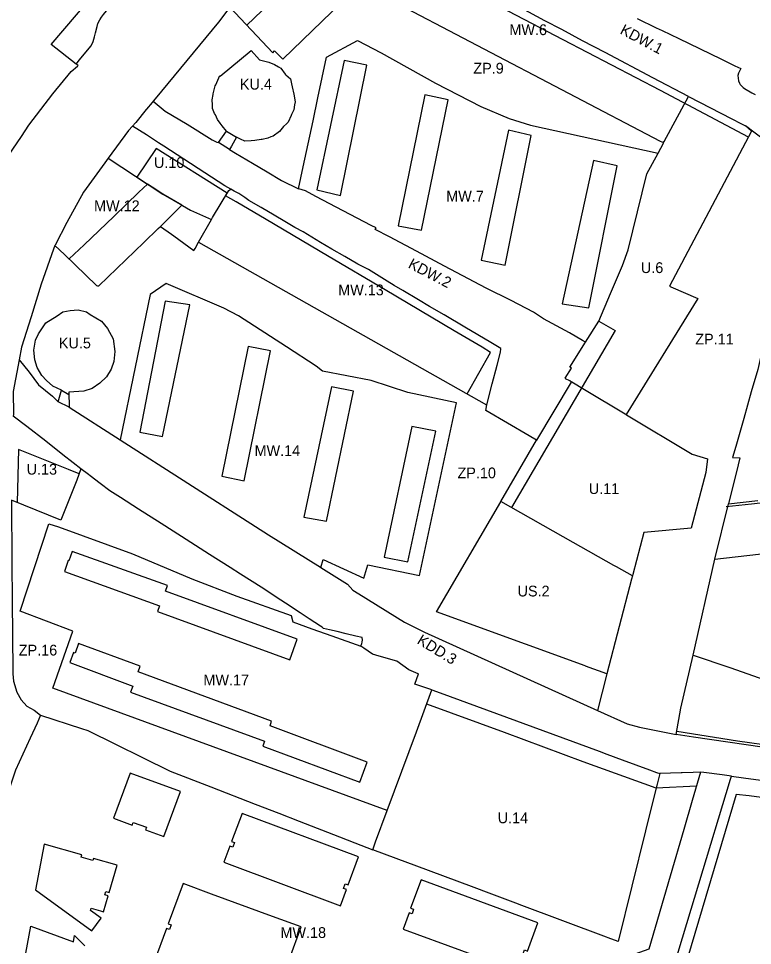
# Model space of a CAD drawing. Extents: x 7428689 to 7430424, y 5549101 to 5550539.
# Drawn here: x 7429558.3 to 7429899, y 5549654.2 to 5550084.5 of the extents above; entities that cross this region are included whole.
import ezdxf

# ---------------------------------------------------------------- set-up
doc = ezdxf.new("R2010")
doc.units = 0
for name, color, linetype in [('linie rozgraniczające', 7, 'Continuous'), ('nieprzekraczalne linie zabudowy', 7, 'Continuous'), ('obowiazujace linie zabudowy', 7, 'Continuous'), ('przeznaczenia terenów', 7, 'Continuous')]:
    doc.layers.add(name, color=color, linetype=linetype)

msp = doc.modelspace()

# ---------------------------------------------------------------- linework, layer by layer
at = {"layer": 'linie rozgraniczające'}
for points in [[(7429585.15, 5550063.36), (7429573.41, 5550072.44), (7429615.16, 5550121.37), (7429623.18, 5550131.69), (7429628.73, 5550142.8), (7429633.73, 5550156.94), (7429637.36, 5550170.6), (7429637.27, 5550178.76), (7429635.82, 5550186.66), (7429632.23, 5550195.98), (7429627.06, 5550204.65), (7429621.44, 5550211.32), (7429578.76, 5550241.61), (7429461.51, 5550318.42), (7429387.53, 5550346.57)], [(7429869.25, 5550048.21), (7429852.78, 5550056.98), (7429830.56, 5550068.73), (7429820.17, 5550074.14), (7429810.58, 5550079.43), (7429802.65, 5550083.47), (7429791.4, 5550089.42), (7429780.49, 5550095.18), (7429764.74, 5550103.58), (7429759.94, 5550106.04), (7429756.81, 5550108.06), (7429752.32, 5550110.84), (7429748.27, 5550113.3), (7429743.03, 5550117.31), (7429741.17, 5550118.66)], [(7429585.15, 5550063.36), (7429586.69, 5550065.24), (7429591.91, 5550071.67), (7429592.5, 5550072.73), (7429592.96, 5550073.85), (7429593.59, 5550076), (7429593.98, 5550077.82), (7429594.75, 5550080.83), (7429595.18, 5550082.22), (7429596.04, 5550083.81), (7429596.76, 5550085.13), (7429597.72, 5550086.32), (7429603.54, 5550093.53), (7429609.86, 5550101.47), (7429615.12, 5550107.92), (7429618.82, 5550112.61), (7429620.13, 5550114.03)], [(7429656.47, 5550089.67), (7429676.37, 5550068.6), (7429677.06, 5550069.42), (7429681.08, 5550065.54), (7429712.8, 5550096.5), (7429725.68, 5550089.53), (7429728.53, 5550094.56)], [(7429728.53, 5550094.56), (7429856.2, 5550027.54), (7429857.77, 5550026.87)], [(7429656.47, 5550089.67), (7429651.14, 5550082.75), (7429621.81, 5550047.22), (7429620.82, 5550046.08)], [(7429845.5, 5550084.48), (7429854.32, 5550080.21), (7429857.1, 5550078.87), (7429864.74, 5550075.17), (7429884.25, 5550065.73), (7429890.82, 5550062.56), (7429893.52, 5550061.26), (7429892.52, 5550059.16), (7429892.26, 5550058.1), (7429892.29, 5550056.74), (7429892.49, 5550055.49), (7429892.92, 5550054.49), (7429893.29, 5550053.87), (7429894.37, 5550052.7), (7429894.69, 5550052.4), (7429895.26, 5550051.95), (7429898.75, 5550050.01), (7429900.22, 5550049.26)], [(7429688.27, 5550005.48), (7429690.46, 5550015.68), (7429695.11, 5550037.01), (7429697.29, 5550047.68), (7429701.34, 5550066.55), (7429715.73, 5550074.25), (7429726.71, 5550068.51), (7429751.94, 5550054.46), (7429772.96, 5550043.69), (7429786.09, 5550038.05), (7429795.94, 5550034.97), (7429855.15, 5550022.01)], [(7429651.13, 5550026.86), (7429654.92, 5550032.22), (7429652.8, 5550034.62), (7429651.9, 5550035.89), (7429650.66, 5550037.64), (7429649.69, 5550039.72), (7429649.35, 5550040.46), (7429648.32, 5550042.77), (7429648.28, 5550044.39), (7429648.21, 5550046.78), (7429648.66, 5550049.14), (7429648.72, 5550049.48), (7429649.67, 5550053.25), (7429649.93, 5550053.77), (7429651.72, 5550057.99), (7429651.92, 5550057.78), (7429666.37, 5550069.7), (7429670.18, 5550065.35), (7429674.49, 5550064.22), (7429677.11, 5550063.11), (7429679, 5550062.04), (7429680.08, 5550061.42), (7429682.04, 5550058.67), (7429682.44, 5550058.31), (7429684.56, 5550056.41), (7429685.07, 5550054.13), (7429685.37, 5550052.78), (7429686.14, 5550049.3), (7429686.73, 5550045.82), (7429686.47, 5550044.37), (7429686.07, 5550042.16), (7429685.08, 5550039.91), (7429684.87, 5550039.44), (7429683.41, 5550036.39), (7429682.66, 5550035.54), (7429681.28, 5550034.29), (7429679.5, 5550032.04), (7429676.45, 5550029.92), (7429675.42, 5550029.52), (7429674, 5550028.95), (7429671.4, 5550028.34), (7429670.93, 5550028.27), (7429668.07, 5550027.81), (7429666.23, 5550027.68), (7429663.32, 5550027.47), (7429661.32, 5550028.49), (7429659.54, 5550029.4), (7429657.11, 5550025.19), (7429656.27, 5550023.71)], [(7429553.73, 5550020.94), (7429559.75, 5550029.69), (7429563.14, 5550035.03), (7429574.24, 5550049.55), (7429582.68, 5550059.88), (7429585.76, 5550062.39), (7429586.07, 5550062.64), (7429585.15, 5550063.36)], [(7429620.82, 5550046.08), (7429620.29, 5550045.47), (7429617.65, 5550042.43), (7429617.5, 5550042.26), (7429612.74, 5550036.22), (7429612.59, 5550036.02), (7429611.21, 5550034.49)], [(7429620.82, 5550046.08), (7429626.45, 5550041.42), (7429636.61, 5550035.39), (7429648.2, 5550028.09), (7429650.34, 5550027.09), (7429651.13, 5550026.86)], [(7429857.77, 5550026.87), (7429858.08, 5550027.46), (7429869.25, 5550048.21)], [(7429869.25, 5550048.21), (7429889.41, 5550037.88), (7429893.56, 5550035.76), (7429895.81, 5550034.62)], [(7429611.21, 5550034.49), (7429609.44, 5550032.52), (7429599.97, 5550019.58)], [(7429656.81, 5550005.3), (7429654.12, 5550006.82), (7429625.7, 5550025.24), (7429623.31, 5550026.82), (7429620.09, 5550028.95), (7429617.74, 5550030.44), (7429611.21, 5550034.49)], [(7429895.81, 5550034.62), (7429898.57, 5550032.25), (7429860.52, 5549960.24), (7429861.09, 5549960), (7429873.67, 5549954.52), (7429840.39, 5549900.6)], [(7429916.81, 5549969.68), (7429907.37, 5549981.28), (7429907.97, 5549984.97), (7429910.62, 5549999.1), (7429912.84, 5550010.27), (7429915.01, 5550020.22), (7429913.54, 5550021.3), (7429904.69, 5550027.9), (7429895.81, 5550034.62)], [(7429656.27, 5550023.71), (7429651.13, 5550026.86)], [(7429855.15, 5550022.01), (7429857.65, 5550026.66), (7429857.7, 5550026.75), (7429857.77, 5550026.87)], [(7429599.97, 5550019.58), (7429598.41, 5550017.45), (7429588.53, 5550003.91), (7429580.8, 5549989.73), (7429575.28, 5549979.34), (7429575.19, 5549979.09)], [(7429599.97, 5550019.58), (7429625.37, 5550002.89), (7429634.45, 5549997.69), (7429638.12, 5549995.59), (7429647.87, 5549991.13)], [(7429656.27, 5550023.71), (7429659.03, 5550022.01), (7429666.97, 5550017.37), (7429673.68, 5550013.28), (7429680.38, 5550009.23), (7429688.27, 5550005.48)], [(7429821.51, 5549934.28), (7429827.64, 5549943.96), (7429833.14, 5549956.88), (7429838.63, 5549969.77), (7429841.32, 5549977.09), (7429849.95, 5550012.35), (7429855.15, 5550022.01)], [(7429647.87, 5549991.13), (7429648.39, 5549992.05), (7429655.88, 5550004.65), (7429656.81, 5550005.3)], [(7429775.71, 5549905.16), (7429778.18, 5549914.86), (7429780.43, 5549923.59), (7429782.03, 5549929.66), (7429782.15, 5549931.13), (7429782.12, 5549931.33), (7429777.49, 5549934.06), (7429765.48, 5549941.2), (7429755.86, 5549946.89), (7429749.11, 5549950.82), (7429744.02, 5549953.83), (7429736.71, 5549958.17), (7429732.74, 5549960.55), (7429729.37, 5549962.63), (7429720.7, 5549967.99), (7429715.87, 5549970.5), (7429709.82, 5549973.94), (7429703.74, 5549977.38), (7429698.51, 5549980.56), (7429690.37, 5549985.39), (7429686.54, 5549987.54), (7429681.97, 5549990.21), (7429676.95, 5549993.16), (7429670.93, 5549996.73), (7429665.27, 5550000.04), (7429663.42, 5550001.36), (7429660.54, 5550003.25), (7429658.48, 5550004.36), (7429656.81, 5550005.3)], [(7429821.51, 5549934.28), (7429820.08, 5549935.1), (7429814.09, 5549938.6), (7429802.03, 5549945.01), (7429797.37, 5549948.18), (7429786.94, 5549953.53), (7429775.41, 5549959.29), (7429761.62, 5549966.57), (7429756.07, 5549969.55), (7429743.09, 5549976.49), (7429730.55, 5549983.08), (7429723.92, 5549986.61), (7429724.28, 5549987.29), (7429722.06, 5549988.44), (7429709.08, 5549995.18), (7429696.34, 5550001.93), (7429691.54, 5550004.51), (7429688.48, 5550005.38), (7429688.27, 5550005.48)], [(7429641.91, 5549980.59), (7429647.87, 5549991.13)], [(7429575.19, 5549979.09), (7429579.7, 5549974.98), (7429594.49, 5549960.54), (7429594.96, 5549960.46), (7429595.63, 5549960.35), (7429616.41, 5549980.48), (7429623.1, 5549986.97), (7429624.28, 5549987.95), (7429629.33, 5549984.32), (7429630.37, 5549983.57), (7429639.77, 5549976.81), (7429640.31, 5549977.78), (7429641.91, 5549980.59)], [(7429575.19, 5549979.09), (7429574.6, 5549977.43), (7429568.87, 5549961.23), (7429564.13, 5549945.96), (7429559.75, 5549931.92), (7429558.64, 5549926.07)], [(7429641.91, 5549980.59), (7429775.53, 5549905.21), (7429775.71, 5549905.16)], [(7429698.6, 5549829.7), (7429699.7, 5549833.33), (7429718.56, 5549824.72), (7429720.51, 5549830.92), (7429744.47, 5549825.99), (7429761.67, 5549906.09), (7429739.1, 5549910.82), (7429722.02, 5549916.42), (7429699.4, 5549920.83), (7429696.47, 5549923.12), (7429682.75, 5549932.04), (7429660.38, 5549946.53), (7429653.56, 5549949.96), (7429626.86, 5549961.43), (7429619.36, 5549956.45), (7429605.47, 5549888.95)], [(7429576.65, 5549906.55), (7429578.22, 5549912.02), (7429574.18, 5549913.77), (7429571.3, 5549916.43), (7429569.09, 5549918.74), (7429567.04, 5549922.44), (7429565.88, 5549926.02), (7429565.47, 5549930.46), (7429566.26, 5549935.15), (7429567.62, 5549938.12), (7429571, 5549943.26), (7429576.28, 5549946.46), (7429578.81, 5549948.33), (7429582.28, 5549949.01), (7429586.07, 5549949.23), (7429589.8, 5549948.28), (7429591.51, 5549947.07), (7429596.84, 5549943.94), (7429599.62, 5549940.56), (7429602.28, 5549935.82), (7429603.01, 5549929.94), (7429602.61, 5549925.21), (7429601.34, 5549921.75), (7429599.11, 5549918.1), (7429595.99, 5549915.26), (7429592.43, 5549912.76), (7429588.61, 5549911.44), (7429581.71, 5549911.07), (7429581.84, 5549904.08)], [(7429908.04, 5549945.59), (7429906.58, 5549941.5), (7429906.31, 5549940.37), (7429905.33, 5549936.24), (7429903.54, 5549929.81), (7429902.43, 5549925.68), (7429901.44, 5549921.63), (7429898.46, 5549911.23), (7429894.97, 5549898.89), (7429891.24, 5549885.87), (7429889.75, 5549880.65), (7429893.15, 5549880.55), (7429892.34, 5549877.29), (7429887.85, 5549859.16)], [(7429815.02, 5549915.74), (7429814.2, 5549916.27), (7429812.23, 5549917.24), (7429812.36, 5549917.46), (7429812.12, 5549917.61), (7429815, 5549922.15), (7429814.16, 5549922.6), (7429821.51, 5549934.28)], [(7429558.64, 5549926.07), (7429555.84, 5549911.31), (7429555.96, 5549900.64), (7429555.91, 5549899.93)], [(7429558.64, 5549926.07), (7429563.23, 5549920.28), (7429565.38, 5549917.32), (7429567.66, 5549914.4), (7429570.78, 5549911.81), (7429574.07, 5549909.18), (7429576.65, 5549906.55)], [(7429798.74, 5549888.73), (7429798.86, 5549888.8), (7429815.02, 5549915.74)], [(7429815.02, 5549915.74), (7429815.08, 5549915.84), (7429820.95, 5549912.3), (7429839.86, 5549900.92), (7429840.29, 5549900.67), (7429840.33, 5549900.64), (7429840.37, 5549900.62), (7429840.39, 5549900.6)], [(7429581.84, 5549904.08), (7429576.65, 5549906.55)], [(7429581.84, 5549904.08), (7429605.47, 5549888.95)], [(7429798.74, 5549888.73), (7429795.33, 5549890.77), (7429795.33, 5549890.77), (7429775.26, 5549902.48), (7429775.7, 5549905.11), (7429775.71, 5549905.16)], [(7429587.28, 5549875.53), (7429583.64, 5549878.26), (7429578.91, 5549881.96), (7429571.02, 5549888.23), (7429562.2, 5549895.06), (7429555.91, 5549899.93)], [(7429840.39, 5549900.6), (7429840.53, 5549900.52), (7429871, 5549882.19), (7429878.11, 5549880.16), (7429877.35, 5549873.76), (7429870.51, 5549847.99), (7429848.5, 5549845.97), (7429843.41, 5549826.45), (7429843.25, 5549825.85)], [(7429605.47, 5549888.95), (7429668.39, 5549848.65), (7429674.4, 5549844.88), (7429698.48, 5549829.77), (7429698.6, 5549829.7)], [(7429782.23, 5549860.32), (7429798.8, 5549888.7), (7429798.74, 5549888.73)], [(7429587.28, 5549875.53), (7429585.37, 5549870.27), (7429577.93, 5549851.65), (7429555.12, 5549860.89)], [(7429717.15, 5549793.18), (7429717.65, 5549794.33), (7429717.83, 5549794.94), (7429717.92, 5549796.1), (7429717.86, 5549797.16), (7429714.91, 5549797.81), (7429710.35, 5549798.91), (7429706.16, 5549799.92), (7429702.65, 5549800.75), (7429699.87, 5549801.38), (7429699.27, 5549801.89), (7429698.41, 5549802.45), (7429693.3, 5549805.81), (7429689.08, 5549808.56), (7429682.25, 5549813.05), (7429680.05, 5549814.49), (7429670.87, 5549820.47), (7429661.35, 5549826.55), (7429656.53, 5549829.67), (7429646.99, 5549835.76), (7429644.78, 5549837.16), (7429634.01, 5549844.04), (7429624.57, 5549850.1), (7429614.01, 5549856.79), (7429605.65, 5549862.11), (7429600.76, 5549865.23), (7429596.23, 5549868.65), (7429591.52, 5549872.22), (7429590.83, 5549872.76), (7429587.28, 5549875.53)], [(7429555.12, 5549860.89), (7429555.15, 5549831.51), (7429555.33, 5549814.51), (7429555.69, 5549781.51), (7429555.75, 5549780.34), (7429555.92, 5549776.94), (7429557.49, 5549771.72), (7429559.59, 5549768.26), (7429562.25, 5549765.37), (7429565.54, 5549763.41), (7429568.57, 5549761.09)], [(7429831.36, 5549780.26), (7429821.48, 5549783.89), (7429821.47, 5549783.87), (7429821.27, 5549783.97), (7429793.68, 5549794.12), (7429752.32, 5549809.11), (7429782.14, 5549860.17), (7429782.23, 5549860.32)], [(7429843.25, 5549825.85), (7429835.93, 5549829.96), (7429834.7, 5549830.53), (7429815.76, 5549841.29), (7429782.23, 5549860.32)], [(7429887.85, 5549859.16), (7429901.45, 5549860.72)], [(7429881.49, 5549833.5), (7429887.85, 5549859.16)], [(7429729.46, 5549716.86), (7429574.24, 5549773.58), (7429583.5, 5549800.05), (7429559.02, 5549809.34), (7429572.42, 5549849.96), (7429576.87, 5549848.51), (7429611.2, 5549835.98), (7429638.72, 5549824.44), (7429659.6, 5549816.36), (7429684.83, 5549807.41), (7429685.69, 5549804.41), (7429694.53, 5549801.26), (7429703.68, 5549797.99), (7429717.15, 5549793.18)], [(7429881.49, 5549833.5), (7429958.54, 5549842.32), (7429958.76, 5549842.35), (7429962.6, 5549842.78), (7429964.4, 5549841.52)], [(7429871.39, 5549789.01), (7429881.49, 5549833.5)], [(7429698.6, 5549829.7), (7429711.07, 5549821.88), (7429713.45, 5549819.07), (7429716.22, 5549817.37), (7429737.5, 5549804.29), (7429739.28, 5549803.41), (7429746.82, 5549799.7), (7429826.99, 5549763.34)], [(7429843.25, 5549825.85), (7429842.81, 5549824.17), (7429831.36, 5549780.26)], [(7429871.39, 5549789.01), (7429888.46, 5549783.29), (7429915.65, 5549773.69), (7429915.92, 5549774.62), (7429916.18, 5549775.67), (7429916.58, 5549776.86), (7429927.23, 5549807.18), (7429960.39, 5549810.65), (7429966.5, 5549811.25)], [(7429750.24, 5549772.92), (7429742.27, 5549775.43), (7429744.01, 5549780.24), (7429743.82, 5549780.31), (7429739.45, 5549782.12), (7429733.95, 5549786.18), (7429730.03, 5549787.31), (7429724.14, 5549789.01), (7429722.65, 5549789.44), (7429718.56, 5549792.22), (7429717.2, 5549793.15), (7429717.18, 5549793.16), (7429717.15, 5549793.18)], [(7429863.62, 5549752.17), (7429865.79, 5549764.38), (7429871.39, 5549789.01)], [(7429831.36, 5549780.26), (7429826.99, 5549763.34)], [(7429729.46, 5549716.86), (7429743.02, 5549753.43), (7429750.24, 5549772.92)], [(7429750.24, 5549772.92), (7429754.07, 5549771.51), (7429827.76, 5549744.4), (7429831.38, 5549743.07), (7429838.58, 5549740.42), (7429851.16, 5549735.8), (7429854.51, 5549734.56), (7429855.96, 5549734.03)], [(7429826.99, 5549763.34), (7429840.89, 5549757.04), (7429846.58, 5549755.58), (7429863.62, 5549752.17)], [(7429568.57, 5549761.09), (7429566.9, 5549757.41), (7429563.77, 5549750.49), (7429556.99, 5549735.53), (7429550.49, 5549716.1), (7429548.76, 5549710.94), (7429543.38, 5549697.43), (7429542.37, 5549694.89), (7429541.35, 5549692.35), (7429533.82, 5549674.3), (7429517.9, 5549636.16)], [(7429568.57, 5549761.09), (7429587.61, 5549754.98), (7429590.55, 5549754.04), (7429628.68, 5549735.16), (7429647.54, 5549727.85), (7429668.13, 5549719.86), (7429679.17, 5549715.57), (7429688.64, 5549711.89), (7429707.29, 5549704.67), (7429714.46, 5549701.87), (7429722.71, 5549698.67)], [(7429974.57, 5549743.68), (7429969.96, 5549745.05), (7429968.9, 5549744.66), (7429967.51, 5549744.92), (7429963.01, 5549746.11), (7429960.03, 5549747.24), (7429956.2, 5549748.63), (7429951.17, 5549747.9), (7429935.89, 5549745.52), (7429925.52, 5549743.92), (7429912.08, 5549744.96), (7429871.59, 5549750.98), (7429863.62, 5549752.17)], [(7429855.96, 5549734.03), (7429854.72, 5549729.03), (7429851.54, 5549716.18), (7429849.36, 5549707.35), (7429836.65, 5549656.01), (7429831.95, 5549657.76), (7429831.26, 5549658.03), (7429811, 5549665.61), (7429790.7, 5549673.21), (7429790.34, 5549673.35), (7429776.79, 5549678.42), (7429769.74, 5549681.06), (7429748.67, 5549688.95), (7429728.18, 5549696.62), (7429722.71, 5549698.67)], [(7429874.89, 5549734.7), (7429871.05, 5549721.57), (7429867.1, 5549708.07), (7429860.77, 5549686.41), (7429850.86, 5549652.48), (7429833.04, 5549646.21), (7429826.11, 5549643.78), (7429821.7, 5549626.48), (7429820.08, 5549620.15), (7429815.04, 5549600.39), (7429808.19, 5549573.55), (7429806.7, 5549567.69), (7429794.73, 5549521.42)], [(7429794.73, 5549521.42), (7429797.12, 5549519.53), (7429807.08, 5549514.9), (7429812.41, 5549529.87), (7429821.23, 5549563.96), (7429822.73, 5549569.85), (7429829.57, 5549596.68), (7429834.43, 5549615.7), (7429834.96, 5549617.8), (7429837.91, 5549624.28), (7429839.87, 5549627.8), (7429842.86, 5549631.59), (7429845.37, 5549632.76), (7429847.45, 5549633.73), (7429851.99, 5549635.55), (7429857.84, 5549637.43), (7429859.86, 5549638.13), (7429860.9, 5549639.29), (7429874.12, 5549682.86), (7429888.83, 5549731.35), (7429889.26, 5549732.78)], [(7429874.89, 5549734.7), (7429871.5, 5549734.58), (7429866.36, 5549734.4), (7429865.82, 5549734.38), (7429855.96, 5549734.03)], [(7429889.26, 5549732.78), (7429885, 5549733.35), (7429876.36, 5549734.5), (7429874.89, 5549734.7)], [(7429889.26, 5549732.78), (7429894.89, 5549732.03), (7429902.84, 5549730.96)], [(7429722.71, 5549698.67), (7429724.04, 5549702.26), (7429729.46, 5549716.86)], [(7429560.16, 5549642.3), (7429563.96, 5549663.23), (7429583.8, 5549655.95), (7429584.34, 5549658.87), (7429589.13, 5549654)]]:
    msp.add_lwpolyline(points, dxfattribs=at)
at = {"layer": 'nieprzekraczalne linie zabudowy'}
for points in [[(7429897.08, 5550029.43), (7429856.35, 5550050.99), (7429811.15, 5550074.65), (7429774.92, 5550093.62), (7429753.78, 5550104.68), (7429737.98, 5550113.04), (7429740.7, 5550118.36), (7429741.17, 5550118.66), (7429714.95, 5550142.63), (7429697.59, 5550122.98), (7429702.3, 5550117.95), (7429664.22, 5550081.46)], [(7429654.92, 5550032.22), (7429659.54, 5550029.4)], [(7429766.58, 5549910.25), (7429777.46, 5549929.53), (7429773.46, 5549931.93), (7429760.54, 5549939.57), (7429728.5, 5549958.49), (7429701.68, 5549974.34), (7429673.24, 5549991.14), (7429659.28, 5549999.39), (7429654.44, 5550002.22), (7429655.19, 5550003.48), (7429622.2, 5550024.07), (7429613.31, 5550010.81), (7429618.12, 5550007.66), (7429614.21, 5550003.83), (7429602.56, 5549992.65), (7429588.78, 5549979.49), (7429581.87, 5549972.98)], [(7429624.28, 5549987.95), (7429634.1, 5549997.89), (7429625.37, 5550002.89), (7429622.05, 5550005.07), (7429618.12, 5550007.66)], [(7429827.64, 5549943.96), (7429835.28, 5549939.73), (7429787.2, 5549857.5)], [(7429578.22, 5549912.02), (7429581.73, 5549909.89)], [(7429586.41, 5549873.13), (7429581.57, 5549875.09), (7429558.37, 5549884.38), (7429557.75, 5549859.82)], [(7430111.57, 5549802.73), (7430095, 5549809.98), (7430066.31, 5549822.5), (7430009.14, 5549847.36), (7429973.71, 5549862.79), (7429955.71, 5549865.8), (7429945.64, 5549864.49), (7429898.6, 5549859.06), (7429886.83, 5549857.85)], [(7429872.96, 5549728.09), (7429872.96, 5549728.09), (7429854.28, 5549727.25), (7429820.43, 5549739.5), (7429783.92, 5549753.02), (7429747.78, 5549766.28)], [(7429863.89, 5549753.68), (7429892, 5549749.19), (7429909.82, 5549746.79), (7429925.29, 5549745.77), (7429964.11, 5549750.56), (7429974.36, 5549747.45)], [(7430250.82, 5549741.6), (7430250.19, 5549740.76), (7430211.41, 5549693.45), (7430176.25, 5549664.73), (7430150.63, 5549651.76), (7430140.11, 5549645.96), (7430038.01, 5549679.61), (7430014.8, 5549687.97), (7429975.18, 5549702.22), (7429941.88, 5549714.17), (7429926.22, 5549719.76), (7429897.47, 5549723.61), (7429891.43, 5549724.32), (7429865.45, 5549636.95), (7429840.64, 5549623.35), (7429816.77, 5549526.64), (7429810.79, 5549500.32)]]:
    msp.add_lwpolyline(points, dxfattribs=at)
at = {"layer": 'obowiazujace linie zabudowy'}
for points in [[(7429709.41, 5550064.98), (7429696.73, 5550004.93), (7429707.76, 5550002.35), (7429719.97, 5550062.77), (7429709.41, 5550064.98)], [(7429745.34, 5549986.28), (7429757.72, 5550046.7), (7429746.85, 5550048.99), (7429734.47, 5549988.24), (7429745.34, 5549986.28)], [(7429784.17, 5549970), (7429796.34, 5550030.18), (7429785.68, 5550032.72), (7429773.05, 5549972.32), (7429784.17, 5549970)], [(7429825.2, 5550018.62), (7429810.71, 5549952.08), (7429823.05, 5549950.16), (7429836.14, 5550016.17), (7429825.2, 5550018.62)], [(7429626.44, 5549953.33), (7429614.62, 5549892.51), (7429625.09, 5549890.49), (7429637.79, 5549951.56), (7429626.44, 5549953.33)], [(7429663.04, 5549869.88), (7429675.21, 5549930.18), (7429664.95, 5549932.28), (7429652.63, 5549872.02), (7429663.04, 5549869.88)], [(7429701.21, 5549851.18), (7429713.86, 5549911.56), (7429703.53, 5549913.58), (7429690.68, 5549853.08), (7429701.21, 5549851.18)], [(7429739.05, 5549832.28), (7429751.97, 5549892.89), (7429740.89, 5549895.13), (7429728.05, 5549834.49), (7429739.05, 5549832.28)], [(7429687.72, 5549796.38), (7429626.49, 5549818.71), (7429627.4, 5549821.33), (7429583.27, 5549837.02), (7429581.62, 5549832.82), (7429581.41, 5549832.89), (7429579.67, 5549827.74), (7429623.77, 5549811.83), (7429622.84, 5549809.3), (7429684.23, 5549786.75), (7429687.72, 5549796.38)], [(7429582.11, 5549785.49), (7429611.4, 5549774.65), (7429610.35, 5549771.72), (7429672.51, 5549749.06), (7429671.77, 5549746.73), (7429716.77, 5549729.98), (7429720.15, 5549739.37), (7429675.07, 5549756.21), (7429675.72, 5549758.34), (7429613.82, 5549781.21), (7429614.75, 5549783.9), (7429586.21, 5549794.43), (7429584.54, 5549789.94), (7429583.82, 5549790.14), (7429582.11, 5549785.49)], [(7429570.28, 5549701.28), (7429566.17, 5549680.01), (7429592.32, 5549660.99), (7429596.66, 5549666.91), (7429591.78, 5549670.49), (7429592.09, 5549671.54), (7429596.41, 5549670.29), (7429597.72, 5549669.9), (7429599.88, 5549677.26), (7429598.44, 5549677.68), (7429598.9, 5549679.3), (7429600.34, 5549678.88), (7429604.03, 5549691.51), (7429593.13, 5549694.65), (7429592.84, 5549693.64), (7429587.44, 5549695.2), (7429587.71, 5549696.24), (7429570.28, 5549701.28)], [(7429634.67, 5549682.96), (7429627.78, 5549664.27), (7429629.19, 5549663.76), (7429628.39, 5549661.59), (7429626.99, 5549662.11), (7429621.26, 5549646.57), (7429634.54, 5549641.72), (7429662.96, 5549631.28), (7429676.17, 5549626.4), (7429683.3, 5549645.83), (7429681.89, 5549646.35), (7429682.69, 5549648.53), (7429684.1, 5549648.02), (7429689.53, 5549662.81), (7429676.28, 5549667.64), (7429647.95, 5549678.07), (7429634.67, 5549682.96)]]:
    msp.add_lwpolyline(points, dxfattribs=at)
for points in [[(7429602.44, 5549713.26), (7429611.06, 5549710.1), (7429611.51, 5549711.32), (7429617.65, 5549709.06), (7429617.22, 5549707.89), (7429625.76, 5549704.72), (7429633.45, 5549725.66), (7429610.11, 5549734.23)], [(7429662.07, 5549715.54), (7429657.15, 5549702.47), (7429658.54, 5549701.96), (7429657.76, 5549699.83), (7429656.4, 5549700.33), (7429653.59, 5549692.82), (7429707.74, 5549672.62), (7429710.5, 5549680.13), (7429709.09, 5549680.65), (7429709.91, 5549682.83), (7429711.31, 5549682.29), (7429716.19, 5549695.33)], [(7429736.79, 5549661.86), (7429790.99, 5549641.94), (7429793.74, 5549649.49), (7429792.34, 5549650), (7429793.16, 5549652.15), (7429794.55, 5549651.61), (7429799.37, 5549664.69), (7429745.18, 5549684.63), (7429740.32, 5549671.53), (7429741.73, 5549671.05), (7429741, 5549668.89), (7429739.59, 5549669.37)]]:
    msp.add_lwpolyline(points, close=True, dxfattribs=at)

# ---------------------------------------------------------------- texts
at = {"layer": 'przeznaczenia terenów'}
for s, p in [('MW.6', (7429786.16, 5550076.78)), ('ZP.9', (7429769.43, 5550058.91)), ('KU.4', (7429661.07, 5550051.48)), ('U.10', (7429621.19, 5550015.12)), ('MW.7', (7429756.83, 5549999.53)), ('MW.12', (7429593.38, 5549995.05)), ('U.6', (7429847.19, 5549966.33)), ('MW.13', (7429706.69, 5549956.01)), ('ZP.11', (7429872.43, 5549933.17)), ('KU.5', (7429577.05, 5549931.36)), ('MW.14', (7429667.88, 5549881.41)), ('U.13', (7429562.09, 5549872.76)), ('ZP.10', (7429762.07, 5549871.06)), ('U.11', (7429823.02, 5549863.77)), ('US.2', (7429789.95, 5549816.22)), ('ZP.16', (7429558.44, 5549788.81)), ('MW.17', (7429644.15, 5549774.95)), ('U.14', (7429780.74, 5549710.96)), ('MW.18', (7429679.9, 5549657.71))]:
    msp.add_text(s, height=5, dxfattribs=at).set_placement(p)
for s, rotation, p in [('KDW.1', 331.9949, (7429837.12, 5550077.65)), ('KDW.2', 332.4135, (7429738.78, 5549969.01)), ('KDD.3', 328.4262, (7429742.92, 5549794.65))]:
    msp.add_text(s, height=5, rotation=rotation, dxfattribs=at).set_placement(p)

doc.saveas('drawing.dxf')
